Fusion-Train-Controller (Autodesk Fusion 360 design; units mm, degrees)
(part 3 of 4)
sketch "Close old plate mounting hole (1)" plane through (24, 0, 0) normal (1, 0, 0) x axis (0, 0, -1)
  circle C1 centre (-44, -51) radius 1.71
extrude "Extrude19" add sketch "Close old plate mounting hole (1)" along normal blind 12
work_plane "WorkPlane20" AlongDistance 23.9 ExtraOffset 0
sketch "Raised M3 block fastener (1)" plane through (23.9, 0, 0) normal (1, 0, 0) x axis (0, 0, -1)
  circle C1 centre (-52, -51) radius 1.7
extrude "Extrude20" cut sketch "Raised M3 block fastener (1)" along normal blind 12.2
work_plane "WorkPlane20" AlongDistance 51.9 ExtraOffset 0
sketch "Continue adjuster bore" plane through (0, 0, 51.9) normal (0, 0, 1) x axis (1, 0, 0)
  circle C1 centre (12, -55) radius 2.2
extrude "Extrude20" cut sketch "Continue adjuster bore" along normal blind 5.2
work_plane "WorkPlane21" AlongDistance 51.9 ExtraOffset 0
sketch "Continue guide bore" plane through (0, 0, 51.9) normal (0, 0, 1) x axis (1, 0, 0)
  circle C1 centre (5, -55) radius 1.7
extrude "Extrude21" cut sketch "Continue guide bore" along normal blind 5.2
work_plane "WorkPlane22" AlongDistance 51.9 ExtraOffset 0
sketch "Continue guide bore (1)" plane through (0, 0, 51.9) normal (0, 0, 1) x axis (1, 0, 0)
  circle C1 centre (19, -55) radius 1.7
extrude "Extrude22" cut sketch "Continue guide bore (1)" along normal blind 5.2
work_plane "WorkPlane23" AlongDistance -24.1 ExtraOffset 0
sketch "Preserve cam sweep clearance" plane through (-24.1, 0, 0) normal (1, 0, 0) x axis (0, 0, -1)
  circle C1 centre (-65, 0) radius 51
extrude "Extrude23" cut sketch "Preserve cam sweep clearance" along normal blind 48.2
work_plane "WorkPlane11" AlongDistance 9 ExtraOffset 0
sketch "Clamp washer clearance at flange" plane through (0, 9, 0) normal (0, 1, 0) x axis (1, 0, 0)
  circle C1 centre (45.5, -73) radius 3.6
extrude "Extrude11" cut sketch "Clamp washer clearance at flange" along normal blind 2
work_plane "WorkPlane8" AlongDistance 37.25 ExtraOffset 0
sketch "Flat shoulder aligns with shaft print bed" plane through (37.25, 0, 0) normal (1, 0, 0) x axis (0, 0, -1)
  line L1 (-54, 11) -> (-54, 6.5)
  line L2 (-76, 11) -> (-54, 11)
  line L3 (-76, 6.5) -> (-76, 11)
  line L4 (-54, 6.5) -> (-76, 6.5)
extrude "Extrude8" cut sketch "Flat shoulder aligns with shaft print bed" along normal blind 3.2
work_plane "WorkPlane1" AlongDistance -23.85 ExtraOffset 0
sketch "Controlled rotor axial clearance" plane through (-23.85, 0, 0) normal (1, 0, 0) x axis (0, 0, -1)
  circle C1 centre (-65, 0) radius 10
extrude "Extrude1" new body sketch "Controlled rotor axial clearance" along normal blind 16.85 bodies "P23 Left rotor thrust spacer"
work_plane "WorkPlane2" AlongDistance -23.95 ExtraOffset 0
sketch "Free spacer bore" plane through (-23.95, 0, 0) normal (1, 0, 0) x axis (0, 0, -1)
  circle C1 centre (-65, 0) radius 8.2
extrude "Extrude2" cut sketch "Free spacer bore" along normal blind 17.05
work_plane "WorkPlane1" AlongDistance 7 ExtraOffset 0
sketch "Controlled rotor axial clearance" plane through (7, 0, 0) normal (1, 0, 0) x axis (0, 0, -1)
  circle C1 centre (-65, 0) radius 10
extrude "Extrude1" new body sketch "Controlled rotor axial clearance" along normal blind 16.85 bodies "P24 Right rotor thrust spacer"
work_plane "WorkPlane2" AlongDistance 6.9 ExtraOffset 0
sketch "Free spacer bore" plane through (6.9, 0, 0) normal (1, 0, 0) x axis (0, 0, -1)
  circle C1 centre (-65, 0) radius 8.2
extrude "Extrude2" cut sketch "Free spacer bore" along normal blind 17.05
work_plane "WorkPlane22" AlongDistance -76 ExtraOffset 0
sketch "Restore rail bolt clearance after hole filling" plane through (0, -76, 0) normal (0, 1, 0) x axis (1, 0, 0)
  circle C1 centre (-30, -45) radius 2.7
extrude "Extrude22" cut sketch "Restore rail bolt clearance after hole filling" along normal blind 22
work_plane "WorkPlane23" AlongDistance 54 ExtraOffset 0
sketch "Restore rail bolt clearance after hole filling (1)" plane through (0, 54, 0) normal (0, 1, 0) x axis (1, 0, 0)
  circle C1 centre (-30, -45) radius 2.7
work_plane "WorkPlane24" AlongDistance -55 ExtraOffset 0
sketch "Restore rail head access after hole filling" plane through (0, -55, 0) normal (0, 1, 0) x axis (1, 0, 0)
  circle C1 centre (-30, -45) radius 5.3
extrude "Extrude24" cut sketch "Restore rail head access after hole filling" along normal blind 12
work_plane "WorkPlane25" AlongDistance 43 ExtraOffset 0
sketch "Restore rail head access after hole filling (1)" plane through (0, 43, 0) normal (0, 1, 0) x axis (1, 0, 0)
  circle C1 centre (-30, -45) radius 5.3
work_plane "WorkPlane21" AlongDistance -76 ExtraOffset 0
sketch "Restore rail bolt clearance after hole filling" plane through (0, -76, 0) normal (0, 1, 0) x axis (1, 0, 0)
  circle C1 centre (30, -45) radius 2.7
extrude "Extrude21" cut sketch "Restore rail bolt clearance after hole filling" along normal blind 22
work_plane "WorkPlane22" AlongDistance 54 ExtraOffset 0
sketch "Restore rail bolt clearance after hole filling (1)" plane through (0, 54, 0) normal (0, 1, 0) x axis (1, 0, 0)
  circle C1 centre (30, -45) radius 2.7
work_plane "WorkPlane23" AlongDistance -55 ExtraOffset 0
sketch "Restore rail head access after hole filling" plane through (0, -55, 0) normal (0, 1, 0) x axis (1, 0, 0)
  circle C1 centre (30, -45) radius 5.3
extrude "Extrude23" cut sketch "Restore rail head access after hole filling" along normal blind 12
work_plane "WorkPlane24" AlongDistance 43 ExtraOffset 0
sketch "Restore rail head access after hole filling (1)" plane through (0, 43, 0) normal (0, 1, 0) x axis (1, 0, 0)
  circle C1 centre (30, -45) radius 5.3
work_plane "WorkPlane14" AlongDistance -18.1 ExtraOffset 0
sketch "Stop lug clearance for concentric thrust spacer" plane through (-18.1, 0, 0) normal (1, 0, 0) x axis (0, 0, -1)
  circle C1 centre (-65, 0) radius 10.2
extrude "Extrude14" cut sketch "Stop lug clearance for concentric thrust spacer" along normal blind 11
work_plane "WorkPlane15" AlongDistance -18.1 ExtraOffset 0
sketch "Complete stop lug relief to rotor face" plane through (-18.1, 0, 0) normal (1, 0, 0) x axis (0, 0, -1)
  circle C1 centre (-65, 0) radius 10.2
extrude "Extrude15" cut sketch "Complete stop lug relief to rotor face" along normal blind 11.1
ground "Pin2"
ground "Pin3"
ground "Pin4"
ground "Pin5"
ground "Pin6"
ground "Pin7"
ground "Pin8"
ground "Pin9"
ground "Pin10"
ground "Pin11"
ground "Pin12"
ground "Pin13"
ground "Pin14"
ground "Pin26"
ground "Pin31"
ground "Pin32"
ground "Pin33"
ground "Pin34"
ground "Pin35"
ground "Pin36"
ground "Pin48"
ground "Pin49"
work_plane "WorkPlane24" AlongDistance -24 ExtraOffset 0
sketch "Extra roof over relocated heat-set inserts" plane through (-24, 0, 0) normal (1, 0, 0) x axis (0, 0, -1)
  line L1 (-57, -44) -> (-57, -66)
  line L2 (-59, -44) -> (-57, -44)
  line L3 (-59, -66) -> (-59, -44)
  line L4 (-57, -66) -> (-59, -66)
extrude "Extrude24" add sketch "Extra roof over relocated heat-set inserts" along normal blind 48
work_plane "WorkPlane25" AlongDistance -24 ExtraOffset 0
sketch "Fill former insert location" plane through (-24, 0, 0) normal (1, 0, 0) x axis (0, 0, -1)
  circle C1 centre (-52, -59) radius 2.01
extrude "Extrude25" add sketch "Fill former insert location" along normal blind 8.7
work_plane "WorkPlane26" AlongDistance 15.3 ExtraOffset 0
sketch "Fill former insert location (1)" plane through (15.3, 0, 0) normal (1, 0, 0) x axis (0, 0, -1)
  circle C1 centre (-52, -59) radius 2.01
extrude "Extrude26" add sketch "Fill former insert location (1)" along normal blind 8.7
work_plane "WorkPlane26" AlongDistance -36 ExtraOffset 0
sketch "Fill former plate mounting hole" plane through (-36, 0, 0) normal (1, 0, 0) x axis (0, 0, -1)
  circle C1 centre (-52, -59) radius 1.71
extrude "Extrude26" add sketch "Fill former plate mounting hole" along normal blind 12
work_plane "WorkPlane25" AlongDistance 24 ExtraOffset 0
sketch "Fill former plate mounting hole" plane through (24, 0, 0) normal (1, 0, 0) x axis (0, 0, -1)
  circle C1 centre (-52, -59) radius 1.71
extrude "Extrude25" add sketch "Fill former plate mounting hole" along normal blind 12
work_plane "WorkPlane27" AlongDistance -24 ExtraOffset 0
sketch "Fill former insert location (2)" plane through (-24, 0, 0) normal (1, 0, 0) x axis (0, 0, -1)
  circle C1 centre (-52, -51) radius 2.01
extrude "Extrude27" add sketch "Fill former insert location (2)" along normal blind 8.7
work_plane "WorkPlane28" AlongDistance 15.3 ExtraOffset 0
sketch "Fill former insert location (3)" plane through (15.3, 0, 0) normal (1, 0, 0) x axis (0, 0, -1)
  circle C1 centre (-52, -51) radius 2.01
extrude "Extrude28" add sketch "Fill former insert location (3)" along normal blind 8.7
work_plane "WorkPlane27" AlongDistance -36 ExtraOffset 0
sketch "Fill former plate mounting hole (1)" plane through (-36, 0, 0) normal (1, 0, 0) x axis (0, 0, -1)
  circle C1 centre (-52, -51) radius 1.71
extrude "Extrude27" add sketch "Fill former plate mounting hole (1)" along normal blind 12
work_plane "WorkPlane26" AlongDistance 24 ExtraOffset 0
sketch "Fill former plate mounting hole (1)" plane through (24, 0, 0) normal (1, 0, 0) x axis (0, 0, -1)
  circle C1 centre (-52, -51) radius 1.71
extrude "Extrude26" add sketch "Fill former plate mounting hole (1)" along normal blind 12
work_plane "WorkPlane29" AlongDistance -24.1 ExtraOffset 0
sketch "Relocated insert with cam-side retaining wall" plane through (-24.1, 0, 0) normal (1, 0, 0) x axis (0, 0, -1)
  circle C1 centre (-53.5, -62) radius 2
extrude "Extrude29" cut sketch "Relocated insert with cam-side retaining wall" along normal blind 8.9
work_plane "WorkPlane30" AlongDistance 15.3 ExtraOffset 0
sketch "Relocated insert with cam-side retaining wall (1)" plane through (15.3, 0, 0) normal (1, 0, 0) x axis (0, 0, -1)
  circle C1 centre (-53.5, -62) radius 2
extrude "Extrude30" cut sketch "Relocated insert with cam-side retaining wall (1)" along normal blind 8.9
work_plane "WorkPlane28" AlongDistance -36.1 ExtraOffset 0
sketch "Relocated mount above rail counterbore" plane through (-36.1, 0, 0) normal (1, 0, 0) x axis (0, 0, -1)
  circle C1 centre (-53.5, -62) radius 1.7
extrude "Extrude28" cut sketch "Relocated mount above rail counterbore" along normal blind 12.2
work_plane "WorkPlane27" AlongDistance 23.9 ExtraOffset 0
sketch "Relocated mount above rail counterbore" plane through (23.9, 0, 0) normal (1, 0, 0) x axis (0, 0, -1)
  circle C1 centre (-53.5, -62) radius 1.7
extrude "Extrude27" cut sketch "Relocated mount above rail counterbore" along normal blind 12.2
work_plane "WorkPlane31" AlongDistance -24.1 ExtraOffset 0
sketch "Relocated insert with cam-side retaining wall (2)" plane through (-24.1, 0, 0) normal (1, 0, 0) x axis (0, 0, -1)
  circle C1 centre (-53.5, -54) radius 2
extrude "Extrude31" cut sketch "Relocated insert with cam-side retaining wall (2)" along normal blind 8.9
work_plane "WorkPlane32" AlongDistance 15.3 ExtraOffset 0
sketch "Relocated insert with cam-side retaining wall (3)" plane through (15.3, 0, 0) normal (1, 0, 0) x axis (0, 0, -1)
  circle C1 centre (-53.5, -54) radius 2
extrude "Extrude32" cut sketch "Relocated insert with cam-side retaining wall (3)" along normal blind 8.9
work_plane "WorkPlane29" AlongDistance -36.1 ExtraOffset 0
sketch "Relocated mount above rail counterbore (1)" plane through (-36.1, 0, 0) normal (1, 0, 0) x axis (0, 0, -1)
  circle C1 centre (-53.5, -54) radius 1.7
extrude "Extrude29" cut sketch "Relocated mount above rail counterbore (1)" along normal blind 12.2
work_plane "WorkPlane28" AlongDistance 23.9 ExtraOffset 0
sketch "Relocated mount above rail counterbore (1)" plane through (23.9, 0, 0) normal (1, 0, 0) x axis (0, 0, -1)
  circle C1 centre (-53.5, -54) radius 1.7
extrude "Extrude28" cut sketch "Relocated mount above rail counterbore (1)" along normal blind 12.2
work_plane "WorkPlane33" AlongDistance 51.9 ExtraOffset 0
sketch "Continue adjuster bore through roof" plane through (0, 0, 51.9) normal (0, 0, 1) x axis (1, 0, 0)
  circle C1 centre (12, -55) radius 2.2
extrude "Extrude33" cut sketch "Continue adjuster bore through roof" along normal blind 7.2
work_plane "WorkPlane34" AlongDistance 51.9 ExtraOffset 0
sketch "Continue guide bore through roof" plane through (0, 0, 51.9) normal (0, 0, 1) x axis (1, 0, 0)
  circle C1 centre (5, -55) radius 1.7
extrude "Extrude34" cut sketch "Continue guide bore through roof" along normal blind 7.2
work_plane "WorkPlane35" AlongDistance 51.9 ExtraOffset 0
sketch "Continue guide bore through roof (1)" plane through (0, 0, 51.9) normal (0, 0, 1) x axis (1, 0, 0)
  circle C1 centre (19, -55) radius 1.7
extrude "Extrude35" cut sketch "Continue guide bore through roof (1)" along normal blind 7.2
work_plane "WorkPlane36" AlongDistance -24.1 ExtraOffset 0
sketch "Restore cam envelope after pocket repair" plane through (-24.1, 0, 0) normal (1, 0, 0) x axis (0, 0, -1)
  circle C1 centre (-65, 0) radius 51
extrude "Extrude36" cut sketch "Restore cam envelope after pocket repair" along normal blind 48.2
work_plane "WorkPlane30" AlongDistance -76 ExtraOffset 0
sketch "Preserve rail shank passage" plane through (0, -76, 0) normal (0, 1, 0) x axis (1, 0, 0)
  circle C1 centre (-30, -45) radius 2.7
work_plane "WorkPlane31" AlongDistance 54 ExtraOffset 0
sketch "Preserve rail shank passage (1)" plane through (0, 54, 0) normal (0, 1, 0) x axis (1, 0, 0)
  circle C1 centre (-30, -45) radius 2.7
work_plane "WorkPlane32" AlongDistance -55 ExtraOffset 0
sketch "Preserve rail head passage" plane through (0, -55, 0) normal (0, 1, 0) x axis (1, 0, 0)
  circle C1 centre (-30, -45) radius 5.3
extrude "Extrude32" cut sketch "Preserve rail head passage" along normal blind 12
work_plane "WorkPlane33" AlongDistance 43 ExtraOffset 0
sketch "Preserve rail head passage (1)" plane through (0, 43, 0) normal (0, 1, 0) x axis (1, 0, 0)
  circle C1 centre (-30, -45) radius 5.3
work_plane "WorkPlane29" AlongDistance -76 ExtraOffset 0
sketch "Preserve rail shank passage" plane through (0, -76, 0) normal (0, 1, 0) x axis (1, 0, 0)
  circle C1 centre (30, -45) radius 2.7
work_plane "WorkPlane30" AlongDistance 54 ExtraOffset 0
sketch "Preserve rail shank passage (1)" plane through (0, 54, 0) normal (0, 1, 0) x axis (1, 0, 0)
  circle C1 centre (30, -45) radius 2.7
work_plane "WorkPlane31" AlongDistance -55 ExtraOffset 0
sketch "Preserve rail head passage" plane through (0, -55, 0) normal (0, 1, 0) x axis (1, 0, 0)
  circle C1 centre (30, -45) radius 5.3
extrude "Extrude31" cut sketch "Preserve rail head passage" along normal blind 12
work_plane "WorkPlane32" AlongDistance 43 ExtraOffset 0
sketch "Preserve rail head passage (1)" plane through (0, 43, 0) normal (0, 1, 0) x axis (1, 0, 0)
  circle C1 centre (30, -45) radius 5.3
work_plane "WorkPlane1" AlongDistance 59 ExtraOffset 0
sketch "One mm extra preload limit" plane through (0, 0, 59) normal (0, 0, 1) x axis (1, 0, 0)
  circle C1 centre (12, -55) radius 3.3
extrude "Extrude1" new body sketch "One mm extra preload limit" along normal blind 2 bodies "P15 Preload limit collar 2 mm"
work_plane "WorkPlane2" AlongDistance 58.9 ExtraOffset 0
sketch "M4 clearance" plane through (0, 0, 58.9) normal (0, 0, 1) x axis (1, 0, 0)
  circle C1 centre (12, -55) radius 2.25
extrude "Extrude2" cut sketch "M4 clearance" along normal blind 2.2
work_plane "WorkPlane1" AlongDistance 32 ExtraOffset 0
sketch "Cup guide M3x35 5" plane through (0, 0, 32) normal (0, 0, 1) x axis (1, 0, 0)
  circle C1 centre (5, -55) radius 1.5
extrude "Extrude1" new body sketch "Cup guide M3x35 5" along normal blind 35 bodies "HARDWARE Cup guide M3x35 5"
work_plane "WorkPlane2" AlongDistance 30.35 ExtraOffset 0
sketch "Button head" plane through (0, 0, 30.35) normal (0, 0, 1) x axis (1, 0, 0)
  circle C1 centre (5, -55) radius 2.85
extrude "Extrude2" add sketch "Button head" along normal blind 1.65
work_plane "WorkPlane1" AlongDistance 59 ExtraOffset 0
sketch "Cup guide washer 5" plane through (0, 0, 59) normal (0, 0, 1) x axis (1, 0, 0)
  circle C1 centre (5, -55) radius 3.5
extrude "Extrude1" new body sketch "Cup guide washer 5" along normal blind 0.5 bodies "HARDWARE Cup guide washer 5"
work_plane "WorkPlane2" AlongDistance 58.9 ExtraOffset 0
sketch "Washer clearance" plane through (0, 0, 58.9) normal (0, 0, 1) x axis (1, 0, 0)
  circle C1 centre (5, -55) radius 1.7
extrude "Extrude2" cut sketch "Washer clearance" along normal blind 0.7
work_plane "WorkPlane1" AlongDistance 59.5 ExtraOffset 0
sketch "Cup guide M3 nut 5" plane through (0, 0, 59.5) normal (0, 0, 1) x axis (1, 0, 0)
  line L1 (6.5877, -52.25) -> (8.1754, -55)
  line L2 (3.4123, -52.25) -> (6.5877, -52.25)
  line L3 (1.8246, -55) -> (3.4123, -52.25)
  line L4 (3.4123, -57.75) -> (1.8246, -55)
  line L5 (6.5877, -57.75) -> (3.4123, -57.75)
  line L6 (8.1754, -55) -> (6.5877, -57.75)
extrude "Extrude1" new body sketch "Cup guide M3 nut 5" along normal blind 2.4 bodies "HARDWARE Cup guide M3 nut 5"
work_plane "WorkPlane2" AlongDistance 59.4 ExtraOffset 0
sketch "Thread envelope" plane through (0, 0, 59.4) normal (0, 0, 1) x axis (1, 0, 0)
  circle C1 centre (5, -55) radius 1.5
extrude "Extrude2" cut sketch "Thread envelope" along normal blind 2.6
work_plane "WorkPlane1" AlongDistance 32 ExtraOffset 0
sketch "Cup guide M3x35 19" plane through (0, 0, 32) normal (0, 0, 1) x axis (1, 0, 0)
  circle C1 centre (19, -55) radius 1.5
extrude "Extrude1" new body sketch "Cup guide M3x35 19" along normal blind 35 bodies "HARDWARE Cup guide M3x35 19"
work_plane "WorkPlane2" AlongDistance 30.35 ExtraOffset 0
sketch "Button head" plane through (0, 0, 30.35) normal (0, 0, 1) x axis (1, 0, 0)
  circle C1 centre (19, -55) radius 2.85
extrude "Extrude2" add sketch "Button head" along normal blind 1.65
work_plane "WorkPlane1" AlongDistance 59 ExtraOffset 0
sketch "Cup guide washer 19" plane through (0, 0, 59) normal (0, 0, 1) x axis (1, 0, 0)
  circle C1 centre (19, -55) radius 3.5
extrude "Extrude1" new body sketch "Cup guide washer 19" along normal blind 0.5 bodies "HARDWARE Cup guide washer 19"
work_plane "WorkPlane2" AlongDistance 58.9 ExtraOffset 0
sketch "Washer clearance" plane through (0, 0, 58.9) normal (0, 0, 1) x axis (1, 0, 0)
  circle C1 centre (19, -55) radius 1.7
extrude "Extrude2" cut sketch "Washer clearance" along normal blind 0.7
work_plane "WorkPlane1" AlongDistance 59.5 ExtraOffset 0
sketch "Cup guide M3 nut 19" plane through (0, 0, 59.5) normal (0, 0, 1) x axis (1, 0, 0)
  line L1 (20.5877, -52.25) -> (22.1754, -55)
  line L2 (17.4123, -52.25) -> (20.5877, -52.25)
  line L3 (15.8246, -55) -> (17.4123, -52.25)
  line L4 (17.4123, -57.75) -> (15.8246, -55)
  line L5 (20.5877, -57.75) -> (17.4123, -57.75)
  line L6 (22.1754, -55) -> (20.5877, -57.75)
extrude "Extrude1" new body sketch "Cup guide M3 nut 19" along normal blind 2.4 bodies "HARDWARE Cup guide M3 nut 19"
work_plane "WorkPlane2" AlongDistance 59.4 ExtraOffset 0
sketch "Thread envelope" plane through (0, 0, 59.4) normal (0, 0, 1) x axis (1, 0, 0)
  circle C1 centre (19, -55) radius 1.5
extrude "Extrude2" cut sketch "Thread envelope" along normal blind 2.6
work_plane "WorkPlane1" AlongDistance -36 ExtraOffset 0
sketch "Spring block M3x20 (-62, -1)" plane through (-36, 0, 0) normal (1, 0, 0) x axis (0, 0, -1)
  circle C1 centre (-53.5, -62) radius 1.5
extrude "Extrude1" new body sketch "Spring block M3x20 (-62, -1)" along normal blind 20 bodies "HARDWARE Spring block M3x20 (-62, -1)"
work_plane "WorkPlane2" AlongDistance -37.65 ExtraOffset 0
sketch "Button head" plane through (-37.65, 0, 0) normal (1, 0, 0) x axis (0, 0, -1)
  circle C1 centre (-53.5, -62) radius 2.85
extrude "Extrude2" add sketch "Button head" along normal blind 1.65
work_plane "WorkPlane1" AlongDistance 16 ExtraOffset 0
sketch "Spring block M3x20 (-62, 1)" plane through (16, 0, 0) normal (1, 0, 0) x axis (0, 0, -1)
  circle C1 centre (-53.5, -62) radius 1.5
extrude "Extrude1" new body sketch "Spring block M3x20 (-62, 1)" along normal blind 20 bodies "HARDWARE Spring block M3x20 (-62, 1)"
work_plane "WorkPlane2" AlongDistance 36 ExtraOffset 0
sketch "Button head" plane through (36, 0, 0) normal (1, 0, 0) x axis (0, 0, -1)
  circle C1 centre (-53.5, -62) radius 2.85
extrude "Extrude2" add sketch "Button head" along normal blind 1.65
work_plane "WorkPlane1" AlongDistance 37 ExtraOffset 0
sketch "Preload adjuster M4x25 SOCKET HEAD" plane through (0, 0, 37) normal (0, 0, 1) x axis (1, 0, 0)
  circle C1 centre (12, -55) radius 2
extrude "Extrude1" new body sketch "Preload adjuster M4x25 SOCKET HEAD" along normal blind 25 bodies "HARDWARE Preload adjuster M4x25 SOCKET HEAD"
work_plane "WorkPlane2" AlongDistance 62 ExtraOffset 0
sketch "Button head" plane through (0, 0, 62) normal (0, 0, 1) x axis (1, 0, 0)
  circle C1 centre (12, -55) radius 3.5
extrude "Extrude2" add sketch "Button head" along normal blind 4
work_plane "WorkPlane16" AlongDistance -5 ExtraOffset 0
sketch "Flat washer seat for sensor-drive shaft clamp" plane through (-5, 0, 0) normal (1, 0, 0) x axis (0, 0, -1)
  line L1 (-60, 22) -> (-60, 20)
  line L2 (-70, 22) -> (-60, 22)
  line L3 (-70, 20) -> (-70, 22)
  line L4 (-60, 20) -> (-70, 20)
extrude "Extrude16" add sketch "Flat washer seat for sensor-drive shaft clamp" along normal blind 10
work_plane "WorkPlane17" AlongDistance 6.4 ExtraOffset 0
sketch "Radial screw onto printed shaft D flat" plane through (0, 6.4, 0) normal (0, 1, 0) x axis (1, 0, 0)
  circle C1 centre (0, -65) radius 1.7
extrude "Extrude17" cut sketch "Radial screw onto printed shaft D flat" along normal blind 15.7
work_plane "WorkPlane18" AlongDistance 15.2 ExtraOffset 0
sketch "M3 heatset pocket for rotor clamp" plane through (0, 15.2, 0) normal (0, 1, 0) x axis (1, 0, 0)
  circle C1 centre (0, -65) radius 2
extrude "Extrude18" cut sketch "M3 heatset pocket for rotor clamp" along normal blind 6.9
work_plane "WorkPlane1" AlongDistance 6.5 ExtraOffset 0
sketch "Rotor clamp M3x16" plane through (0, 6.5, 0) normal (0, 1, 0) x axis (1, 0, 0)
  circle C1 centre (0, -65) radius 1.5
extrude "Extrude1" new body sketch "Rotor clamp M3x16" along normal blind 16 bodies "HARDWARE Rotor clamp M3x16"
work_plane "WorkPlane2" AlongDistance 22.5 ExtraOffset 0
sketch "Button head" plane through (0, 22.5, 0) normal (0, 1, 0) x axis (1, 0, 0)
  circle C1 centre (0, -65) radius 2.85
extrude "Extrude2" add sketch "Button head" along normal blind 1.65
work_plane "WorkPlane1" AlongDistance 22 ExtraOffset 0
sketch "Rotor clamp M3 washer" plane through (0, 22, 0) normal (0, 1, 0) x axis (1, 0, 0)
  circle C1 centre (0, -65) radius 3.5
extrude "Extrude1" new body sketch "Rotor clamp M3 washer" along normal blind 0.5 bodies "HARDWARE Rotor clamp M3 washer"
work_plane "WorkPlane2" AlongDistance 21.9 ExtraOffset 0
sketch "Washer clearance" plane through (0, 21.9, 0) normal (0, 1, 0) x axis (1, 0, 0)
  circle C1 centre (0, -65) radius 1.7
extrude "Extrude2" cut sketch "Washer clearance" along normal blind 0.7
work_plane "WorkPlane4" AlongDistance 51.9 ExtraOffset 0
sketch "Input slot 4.2 mm - tune running fit" plane through (51.9, 0, 0) normal (1, 0, 0) x axis (0, 0, -1)
  line L1 (-62.9, 13) -> (-62.9, -13)
  line L2 (-67.1, 13) -> (-62.9, 13)
  line L3 (-67.1, -13) -> (-67.1, 13)
  line L4 (-62.9, -13) -> (-67.1, -13)
extrude "Extrude4" cut sketch "Input slot 4.2 mm - tune running fit" along normal blind 2.6
work_plane "WorkPlane5" AlongDistance 57.5 ExtraOffset 0
sketch "Output slot 4.2 mm - tune running fit" plane through (57.5, 0, 0) normal (1, 0, 0) x axis (0, 0, -1)
  line L1 (-52, 2.1) -> (-52, -2.1)
  line L2 (-78, 2.1) -> (-52, 2.1)
  line L3 (-78, -2.1) -> (-78, 2.1)
  line L4 (-52, -2.1) -> (-78, -2.1)
extrude "Extrude5" cut sketch "Output slot 4.2 mm - tune running fit" along normal blind 2.6
work_plane "WorkPlane1" AlongDistance 52 ExtraOffset 0
sketch "Optional closer running fit" plane through (52, 0, 0) normal (1, 0, 0) x axis (0, 0, -1)
  circle C1 centre (-65, 0) radius 12
extrude "Extrude1" new body sketch "Optional closer running fit" along normal blind 8 bodies "P18 Tight fit alternate disc - 4.1 mm slots"
work_plane "WorkPlane2" AlongDistance 51.9 ExtraOffset 0
sketch "Input 4.1 slot" plane through (51.9, 0, 0) normal (1, 0, 0) x axis (0, 0, -1)
  line L1 (-62.95, 13) -> (-62.95, -13)
  line L2 (-67.05, 13) -> (-62.95, 13)
  line L3 (-67.05, -13) -> (-67.05, 13)
  line L4 (-62.95, -13) -> (-67.05, -13)
extrude "Extrude2" cut sketch "Input 4.1 slot" along normal blind 2.6
work_plane "WorkPlane3" AlongDistance 57.5 ExtraOffset 0
sketch "Output 4.1 slot" plane through (57.5, 0, 0) normal (1, 0, 0) x axis (0, 0, -1)
  line L1 (-52, 2.05) -> (-52, -2.05)
  line L2 (-78, 2.05) -> (-52, 2.05)
  line L3 (-78, -2.05) -> (-78, 2.05)
  line L4 (-52, -2.05) -> (-78, -2.05)
extrude "Extrude3" cut sketch "Output 4.1 slot" along normal blind 2.6
work_plane "WorkPlane37" AlongDistance -24 ExtraOffset 0
sketch "Extend reaction block into free rail bay" plane through (-24, 0, 0) normal (1, 0, 0) x axis (0, 0, -1)
  line L1 (-38, -66) -> (-38, -74)
  line L2 (-59, -66) -> (-38, -66)
  line L3 (-59, -74) -> (-59, -66)
  line L4 (-38, -74) -> (-59, -74)
extrude "Extrude37" add sketch "Extend reaction block into free rail bay" along normal blind 48
work_plane "WorkPlane38" AlongDistance -24 ExtraOffset 0
sketch "Close mounting bore that crossed cup guide" plane through (-24, 0, 0) normal (1, 0, 0) x axis (0, 0, -1)
  circle C1 centre (-53.5, -54) radius 2.01
extrude "Extrude38" add sketch "Close mounting bore that crossed cup guide" along normal blind 8.7
work_plane "WorkPlane39" AlongDistance -24.1 ExtraOffset 0
sketch "Outer mounting row clear of guide" plane through (-24.1, 0, 0) normal (1, 0, 0) x axis (0, 0, -1)
  circle C1 centre (-53.5, -70) radius 2
extrude "Extrude39" cut sketch "Outer mounting row clear of guide" along normal blind 8.9
work_plane "WorkPlane40" AlongDistance 15.3 ExtraOffset 0
sketch "Close mounting bore that crossed cup guide (1)" plane through (15.3, 0, 0) normal (1, 0, 0) x axis (0, 0, -1)
  circle C1 centre (-53.5, -54) radius 2.01
extrude "Extrude40" add sketch "Close mounting bore that crossed cup guide (1)" along normal blind 8.7
work_plane "WorkPlane41" AlongDistance 15.2 ExtraOffset 0
sketch "Outer mounting row clear of guide (1)" plane through (15.2, 0, 0) normal (1, 0, 0) x axis (0, 0, -1)
  circle C1 centre (-53.5, -70) radius 2
extrude "Extrude41" cut sketch "Outer mounting row clear of guide (1)" along normal blind 8.9
work_plane "WorkPlane34" AlongDistance -36 ExtraOffset 0
sketch "Close former inner mounting hole" plane through (-36, 0, 0) normal (1, 0, 0) x axis (0, 0, -1)
  circle C1 centre (-53.5, -54) radius 1.71
extrude "Extrude34" add sketch "Close former inner mounting hole" along normal blind 12
work_plane "WorkPlane35" AlongDistance -36.1 ExtraOffset 0
sketch "Matched outer mounting row" plane through (-36.1, 0, 0) normal (1, 0, 0) x axis (0, 0, -1)
  circle C1 centre (-53.5, -70) radius 1.7
extrude "Extrude35" cut sketch "Matched outer mounting row" along normal blind 12.2
work_plane "WorkPlane33" AlongDistance 24 ExtraOffset 0
sketch "Close former inner mounting hole" plane through (24, 0, 0) normal (1, 0, 0) x axis (0, 0, -1)
  circle C1 centre (-53.5, -54) radius 1.71
extrude "Extrude33" add sketch "Close former inner mounting hole" along normal blind 12
work_plane "WorkPlane34" AlongDistance 23.9 ExtraOffset 0
sketch "Matched outer mounting row" plane through (23.9, 0, 0) normal (1, 0, 0) x axis (0, 0, -1)
  circle C1 centre (-53.5, -70) radius 1.7
extrude "Extrude34" cut sketch "Matched outer mounting row" along normal blind 12.2
work_plane "WorkPlane42" AlongDistance 37.9 ExtraOffset 0
sketch "Restore separate cup guide bore" plane through (0, 0, 37.9) normal (0, 0, 1) x axis (1, 0, 0)
  circle C1 centre (5, -55) radius 1.7
work_plane "WorkPlane43" AlongDistance 37.9 ExtraOffset 0
sketch "Restore separate cup guide bore (1)" plane through (0, 0, 37.9) normal (0, 0, 1) x axis (1, 0, 0)
  circle C1 centre (19, -55) radius 1.7
extrude "Extrude43" cut sketch "Restore separate cup guide bore (1)" along normal blind 21.2
work_plane "WorkPlane44" AlongDistance -24.1 ExtraOffset 0
sketch "Preserve cam envelope" plane through (-24.1, 0, 0) normal (1, 0, 0) x axis (0, 0, -1)
  circle C1 centre (-65, 0) radius 51
work_plane "WorkPlane1" AlongDistance -36 ExtraOffset 0
sketch "Spring block M3x20 (-70, -1)" plane through (-36, 0, 0) normal (1, 0, 0) x axis (0, 0, -1)
  circle C1 centre (-53.5, -70) radius 1.5
extrude "Extrude1" new body sketch "Spring block M3x20 (-70, -1)" along normal blind 20 bodies "HARDWARE Spring block M3x20 (-70, -1)"
work_plane "WorkPlane2" AlongDistance -37.65 ExtraOffset 0
sketch "Button head" plane through (-37.65, 0, 0) normal (1, 0, 0) x axis (0, 0, -1)
  circle C1 centre (-53.5, -70) radius 2.85
extrude "Extrude2" add sketch "Button head" along normal blind 1.65
work_plane "WorkPlane1" AlongDistance 16 ExtraOffset 0
sketch "Spring block M3x20 (-70, 1)" plane through (16, 0, 0) normal (1, 0, 0) x axis (0, 0, -1)
  circle C1 centre (-53.5, -70) radius 1.5
extrude "Extrude1" new body sketch "Spring block M3x20 (-70, 1)" along normal blind 20 bodies "HARDWARE Spring block M3x20 (-70, 1)"
work_plane "WorkPlane2" AlongDistance 36 ExtraOffset 0
sketch "Button head" plane through (36, 0, 0) normal (1, 0, 0) x axis (0, 0, -1)
  circle C1 centre (-53.5, -70) radius 2.85
extrude "Extrude2" add sketch "Button head" along normal blind 1.65
ground "Pin50"
ground "Pin51"
ground "Pin52"
ground "Pin53"
ground "Pin54"
ground "Pin55"
ground "Pin56"
ground "Pin57"
ground "Pin58"
ground "Pin59"
ground "Pin68"
ground "Pin69"
as_built_joint "As-built6"
as_built_joint "As-built7"
as_built_joint "As-built8" RotateMinimum -52 RotateMaximum 52
as_built_joint "As-built9" RotateMinimum -6 RotateMaximum 1
as_built_joint "As-built10"
work_plane "WorkPlane36" AlongDistance -55 ExtraOffset 0
sketch "Close inaccessible rail head pocket" plane through (0, -55, 0) normal (0, 1, 0) x axis (1, 0, 0)
  circle C1 centre (-30, -45) radius 5.31
extrude "Extrude36" add sketch "Close inaccessible rail head pocket" along normal blind 12
work_plane "WorkPlane37" AlongDistance 43 ExtraOffset 0
sketch "Close inaccessible rail head pocket (1)" plane through (0, 43, 0) normal (0, 1, 0) x axis (1, 0, 0)
  circle C1 centre (-30, -45) radius 5.31
extrude "Extrude37" add sketch "Close inaccessible rail head pocket (1)" along normal blind 12
work_plane "WorkPlane38" AlongDistance -75 ExtraOffset 0
sketch "Close obsolete side rail bore" plane through (0, -75, 0) normal (0, 1, 0) x axis (1, 0, 0)
  circle C1 centre (-30, -45) radius 2.71
extrude "Extrude38" add sketch "Close obsolete side rail bore" along normal blind 20
work_plane "WorkPlane39" AlongDistance 55 ExtraOffset 0
sketch "Close obsolete side rail bore (1)" plane through (0, 55, 0) normal (0, 1, 0) x axis (1, 0, 0)
  circle C1 centre (-30, -45) radius 2.71
extrude "Extrude39" add sketch "Close obsolete side rail bore (1)" along normal blind 20
work_plane "WorkPlane40" AlongDistance -36 ExtraOffset 0
sketch "Top-access 2020 mounting flange" plane through (-36, 0, 0) normal (1, 0, 0) x axis (0, 0, -1)
  line L1 (-55, -70) -> (-55, -95)
  line L2 (-63, -70) -> (-55, -70)
  line L3 (-63, -95) -> (-63, -70)
  line L4 (-55, -95) -> (-63, -95)
extrude "Extrude40" add sketch "Top-access 2020 mounting flange" along normal blind 12
work_plane "WorkPlane41" AlongDistance -36 ExtraOffset 0
sketch "Mount root triangular reinforcement" plane through (-36, 0, 0) normal (1, 0, 0) x axis (0, 0, -1)
  line L1 (-56, -63) -> (-56, -70)
  line L2 (-63, -70) -> (-56, -63)
  line L3 (-56, -70) -> (-63, -70)
extrude "Extrude41" add sketch "Mount root triangular reinforcement" along normal blind 12
work_plane "WorkPlane42" AlongDistance 54.9 ExtraOffset 0
sketch "Vertical M5 rail mounting bore" plane through (0, 0, 54.9) normal (0, 0, 1) x axis (1, 0, 0)
  circle C1 centre (-30, -85) radius 2.7
extrude "Extrude42" cut sketch "Vertical M5 rail mounting bore" along normal blind 8.2
work_plane "WorkPlane43" AlongDistance -36 ExtraOffset 0
sketch "Top-access 2020 mounting flange (1)" plane through (-36, 0, 0) normal (1, 0, 0) x axis (0, 0, -1)
  line L1 (-55, 95) -> (-55, 70)
  line L2 (-63, 95) -> (-55, 95)
  line L3 (-63, 70) -> (-63, 95)
  line L4 (-55, 70) -> (-63, 70)
extrude "Extrude43" add sketch "Top-access 2020 mounting flange (1)" along normal blind 12
work_plane "WorkPlane44" AlongDistance -36 ExtraOffset 0
sketch "Mount root triangular reinforcement (1)" plane through (-36, 0, 0) normal (1, 0, 0) x axis (0, 0, -1)
  line L1 (-56, 70) -> (-56, 63)
  line L2 (-63, 70) -> (-56, 70)
  line L3 (-56, 63) -> (-63, 70)
extrude "Extrude44" add sketch "Mount root triangular reinforcement (1)" along normal blind 12
work_plane "WorkPlane45" AlongDistance 54.9 ExtraOffset 0
sketch "Vertical M5 rail mounting bore (1)" plane through (0, 0, 54.9) normal (0, 0, 1) x axis (1, 0, 0)
  circle C1 centre (-30, 85) radius 2.7
extrude "Extrude45" cut sketch "Vertical M5 rail mounting bore (1)" along normal blind 8.2
work_plane "WorkPlane46" AlongDistance -36 ExtraOffset 0
sketch "Close old M5 pivot clearance" plane through (-36, 0, 0) normal (1, 0, 0) x axis (0, 0, -1)
  circle C1 centre (-12, -35) radius 2.71
extrude "Extrude46" add sketch "Close old M5 pivot clearance" along normal blind 12
work_plane "WorkPlane47" AlongDistance -36.1 ExtraOffset 0
sketch "M3 follower pivot clearance" plane through (-36.1, 0, 0) normal (1, 0, 0) x axis (0, 0, -1)
  circle C1 centre (-12, -35) radius 1.7
extrude "Extrude47" cut sketch "M3 follower pivot clearance" along normal blind 12.2
work_plane "WorkPlane35" AlongDistance -55 ExtraOffset 0
sketch "Close inaccessible rail head pocket" plane through (0, -55, 0) normal (0, 1, 0) x axis (1, 0, 0)
  circle C1 centre (30, -45) radius 5.31
extrude "Extrude35" add sketch "Close inaccessible rail head pocket" along normal blind 12
work_plane "WorkPlane36" AlongDistance 43 ExtraOffset 0
sketch "Close inaccessible rail head pocket (1)" plane through (0, 43, 0) normal (0, 1, 0) x axis (1, 0, 0)
  circle C1 centre (30, -45) radius 5.31
extrude "Extrude36" add sketch "Close inaccessible rail head pocket (1)" along normal blind 12
work_plane "WorkPlane37" AlongDistance -75 ExtraOffset 0
sketch "Close obsolete side rail bore" plane through (0, -75, 0) normal (0, 1, 0) x axis (1, 0, 0)
  circle C1 centre (30, -45) radius 2.71
extrude "Extrude37" add sketch "Close obsolete side rail bore" along normal blind 20
work_plane "WorkPlane38" AlongDistance 55 ExtraOffset 0
sketch "Close obsolete side rail bore (1)" plane through (0, 55, 0) normal (0, 1, 0) x axis (1, 0, 0)
  circle C1 centre (30, -45) radius 2.71
extrude "Extrude38" add sketch "Close obsolete side rail bore (1)" along normal blind 20
work_plane "WorkPlane39" AlongDistance 24 ExtraOffset 0
sketch "Top-access 2020 mounting flange" plane through (24, 0, 0) normal (1, 0, 0) x axis (0, 0, -1)
  line L1 (-55, -70) -> (-55, -95)
  line L2 (-63, -70) -> (-55, -70)
  line L3 (-63, -95) -> (-63, -70)
  line L4 (-55, -95) -> (-63, -95)
extrude "Extrude39" add sketch "Top-access 2020 mounting flange" along normal blind 12
work_plane "WorkPlane40" AlongDistance 24 ExtraOffset 0
sketch "Mount root triangular reinforcement" plane through (24, 0, 0) normal (1, 0, 0) x axis (0, 0, -1)
  line L1 (-56, -63) -> (-56, -70)
  line L2 (-63, -70) -> (-56, -63)
  line L3 (-56, -70) -> (-63, -70)
extrude "Extrude40" add sketch "Mount root triangular reinforcement" along normal blind 12
work_plane "WorkPlane41" AlongDistance 54.9 ExtraOffset 0
sketch "Vertical M5 rail mounting bore" plane through (0, 0, 54.9) normal (0, 0, 1) x axis (1, 0, 0)
  circle C1 centre (30, -85) radius 2.7
extrude "Extrude41" cut sketch "Vertical M5 rail mounting bore" along normal blind 8.2
work_plane "WorkPlane42" AlongDistance 24 ExtraOffset 0
sketch "Top-access 2020 mounting flange (1)" plane through (24, 0, 0) normal (1, 0, 0) x axis (0, 0, -1)
  line L1 (-55, 95) -> (-55, 70)
  line L2 (-63, 95) -> (-55, 95)
  line L3 (-63, 70) -> (-63, 95)
  line L4 (-55, 70) -> (-63, 70)
extrude "Extrude42" add sketch "Top-access 2020 mounting flange (1)" along normal blind 12
work_plane "WorkPlane43" AlongDistance 24 ExtraOffset 0
sketch "Mount root triangular reinforcement (1)" plane through (24, 0, 0) normal (1, 0, 0) x axis (0, 0, -1)
  line L1 (-56, 70) -> (-56, 63)
  line L2 (-63, 70) -> (-56, 70)
  line L3 (-56, 63) -> (-63, 70)
extrude "Extrude43" add sketch "Mount root triangular reinforcement (1)" along normal blind 12
work_plane "WorkPlane44" AlongDistance 54.9 ExtraOffset 0
sketch "Vertical M5 rail mounting bore (1)" plane through (0, 0, 54.9) normal (0, 0, 1) x axis (1, 0, 0)
  circle C1 centre (30, 85) radius 2.7
extrude "Extrude44" cut sketch "Vertical M5 rail mounting bore (1)" along normal blind 8.2
work_plane "WorkPlane45" AlongDistance 24 ExtraOffset 0
sketch "Close old M5 pivot clearance" plane through (24, 0, 0) normal (1, 0, 0) x axis (0, 0, -1)
  circle C1 centre (-12, -35) radius 2.71
extrude "Extrude45" add sketch "Close old M5 pivot clearance" along normal blind 12
work_plane "WorkPlane46" AlongDistance 23.9 ExtraOffset 0
sketch "M3 follower pivot clearance" plane through (23.9, 0, 0) normal (1, 0, 0) x axis (0, 0, -1)
  circle C1 centre (-12, -35) radius 1.7
extrude "Extrude46" cut sketch "M3 follower pivot clearance" along normal blind 12.2
work_plane "WorkPlane47" AlongDistance 23.9 ExtraOffset 0
sketch "Restore cam service opening after obsolete bore closure" plane through (23.9, 0, 0) normal (1, 0, 0) x axis (0, 0, -1)
  line L1 (-42.2047, 46.7373) -> (-43.8497, 47.5044)
  line L2 (-40.5875, 45.9133) -> (-42.2047, 46.7373)
  line L3 (-39, 45.0333) -> (-40.5875, 45.9133)
  line L4 (-37.4442, 44.0985) -> (-39, 45.0333)
  line L5 (-35.922, 43.11) -> (-37.4442, 44.0985)
  line L6 (-34.4352, 42.0689) -> (-35.922, 43.11)
  line L7 (-32.9856, 40.9766) -> (-34.4352, 42.0689)
  line L8 (-31.575, 39.8343) -> (-32.9856, 40.9766)
  line L9 (-30.2052, 38.6435) -> (-31.575, 39.8343)
  line L10 (-28.8778, 37.4057) -> (-30.2052, 38.6435)
  line L11 (-27.5943, 36.1222) -> (-28.8778, 37.4057)
  line L12 (-26.3565, 34.7948) -> (-27.5943, 36.1222)
  line L13 (-25.1657, 33.425) -> (-26.3565, 34.7948)
  line L14 (-24.0234, 32.0144) -> (-25.1657, 33.425)
  line L15 (-22.9311, 30.5648) -> (-24.0234, 32.0144)
  line L16 (-21.89, 29.078) -> (-22.9311, 30.5648)
  line L17 (-20.9015, 27.5558) -> (-21.89, 29.078)
  line L18 (-19.9667, 26) -> (-20.9015, 27.5558)
  line L19 (-19.0867, 24.4125) -> (-19.9667, 26)
  line L20 (-18.2627, 22.7953) -> (-19.0867, 24.4125)
  line L21 (-17.4956, 21.1503) -> (-18.2627, 22.7953)
  line L22 (-16.7864, 19.4795) -> (-17.4956, 21.1503)
  line L23 (-16.136, 17.785) -> (-16.7864, 19.4795)
  line L24 (-15.5451, 16.0689) -> (-16.136, 17.785)
  line L25 (-15.0144, 14.3331) -> (-15.5451, 16.0689)
  line L26 (-14.5446, 12.5799) -> (-15.0144, 14.3331)
  line L27 (-14.1363, 10.8114) -> (-14.5446, 12.5799)
  line L28 (-13.79, 9.0297) -> (-14.1363, 10.8114)
  line L29 (-13.5061, 7.237) -> (-13.79, 9.0297)
  line L30 (-13.2849, 5.4355) -> (-13.5061, 7.237)
  line L31 (-13.1267, 3.6273) -> (-13.2849, 5.4355)
  line L32 (-13.0317, 1.8148) -> (-13.1267, 3.6273)
  line L33 (-13, 0) -> (-13.0317, 1.8148)
  line L34 (-13.0317, -1.8148) -> (-13, 0)
  line L35 (-13.1267, -3.6273) -> (-13.0317, -1.8148)
  line L36 (-13.2849, -5.4355) -> (-13.1267, -3.6273)
  line L37 (-13.5061, -7.237) -> (-13.2849, -5.4355)
  line L38 (-13.79, -9.0297) -> (-13.5061, -7.237)
  line L39 (-14.1363, -10.8114) -> (-13.79, -9.0297)
  line L40 (-14.5446, -12.5799) -> (-14.1363, -10.8114)
  line L41 (-15.0144, -14.3331) -> (-14.5446, -12.5799)
  line L42 (-15.5451, -16.0689) -> (-15.0144, -14.3331)
  line L43 (-16.136, -17.785) -> (-15.5451, -16.0689)
  line L44 (-16.7864, -19.4795) -> (-16.136, -17.785)
  line L45 (-17.4956, -21.1503) -> (-16.7864, -19.4795)
  line L46 (-18.2627, -22.7953) -> (-17.4956, -21.1503)
  line L47 (-19.0867, -24.4125) -> (-18.2627, -22.7953)
  line L48 (-19.9667, -26) -> (-19.0867, -24.4125)
  line L49 (-20.9015, -27.5558) -> (-19.9667, -26)
  line L50 (-21.89, -29.078) -> (-20.9015, -27.5558)
  line L51 (-22.9311, -30.5648) -> (-21.89, -29.078)
  line L52 (-24.0234, -32.0144) -> (-22.9311, -30.5648)
  line L53 (-25.1657, -33.425) -> (-24.0234, -32.0144)
  line L54 (-26.3565, -34.7948) -> (-25.1657, -33.425)
  line L55 (-27.5943, -36.1222) -> (-26.3565, -34.7948)
  line L56 (-28.8778, -37.4057) -> (-27.5943, -36.1222)
  line L57 (-30.2052, -38.6435) -> (-28.8778, -37.4057)
  line L58 (-31.575, -39.8343) -> (-30.2052, -38.6435)
  line L59 (-32.9856, -40.9766) -> (-31.575, -39.8343)
  line L60 (-34.4352, -42.0689) -> (-32.9856, -40.9766)
  line L61 (-35.922, -43.11) -> (-34.4352, -42.0689)
  line L62 (-37.4442, -44.0985) -> (-35.922, -43.11)
  line L63 (-39, -45.0333) -> (-37.4442, -44.0985)
  line L64 (-40.5875, -45.9133) -> (-39, -45.0333)
  line L65 (-42.2047, -46.7373) -> (-40.5875, -45.9133)
  line L66 (-43.8497, -47.5044) -> (-42.2047, -46.7373)
  line L67 (-54.4248, -23.7522) -> (-43.8497, -47.5044)
  line L68 (-53.6024, -23.3686) -> (-54.4248, -23.7522)
  line L69 (-52.7937, -22.9566) -> (-53.6024, -23.3686)
  line L70 (-52, -22.5167) -> (-52.7937, -22.9566)
  line L71 (-51.2221, -22.0493) -> (-52, -22.5167)
  line L72 (-50.461, -21.555) -> (-51.2221, -22.0493)
  line L73 (-49.7176, -21.0344) -> (-50.461, -21.555)
  line L74 (-48.9928, -20.4883) -> (-49.7176, -21.0344)
  line L75 (-48.2875, -19.9172) -> (-48.9928, -20.4883)
  line L76 (-47.6026, -19.3218) -> (-48.2875, -19.9172)
  line L77 (-46.9389, -18.7028) -> (-47.6026, -19.3218)
  line L78 (-46.2972, -18.0611) -> (-46.9389, -18.7028)
  line L79 (-45.6782, -17.3974) -> (-46.2972, -18.0611)
  line L80 (-45.0828, -16.7125) -> (-45.6782, -17.3974)
  line L81 (-44.5117, -16.0072) -> (-45.0828, -16.7125)
  line L82 (-43.9656, -15.2824) -> (-44.5117, -16.0072)
  line L83 (-43.445, -14.539) -> (-43.9656, -15.2824)
  line L84 (-42.9507, -13.7779) -> (-43.445, -14.539)
  line L85 (-42.4833, -13) -> (-42.9507, -13.7779)
  line L86 (-42.0434, -12.2063) -> (-42.4833, -13)
  line L87 (-41.6314, -11.3976) -> (-42.0434, -12.2063)
  line L88 (-41.2478, -10.5752) -> (-41.6314, -11.3976)
  line L89 (-40.8932, -9.7398) -> (-41.2478, -10.5752)
  line L90 (-40.568, -8.8925) -> (-40.8932, -9.7398)
  line L91 (-40.2725, -8.0344) -> (-40.568, -8.8925)
  line L92 (-40.0072, -7.1666) -> (-40.2725, -8.0344)
  line L93 (-39.7723, -6.29) -> (-40.0072, -7.1666)
  line L94 (-39.5682, -5.4057) -> (-39.7723, -6.29)
  line L95 (-39.395, -4.5149) -> (-39.5682, -5.4057)
  line L96 (-39.253, -3.6185) -> (-39.395, -4.5149)
  line L97 (-39.1424, -2.7177) -> (-39.253, -3.6185)
  line L98 (-39.0633, -1.8137) -> (-39.1424, -2.7177)
  line L99 (-39.0158, -0.9074) -> (-39.0633, -1.8137)
  line L100 (-39, 0) -> (-39.0158, -0.9074)
  line L101 (-39.0158, 0.9074) -> (-39, 0)
  line L102 (-39.0633, 1.8137) -> (-39.0158, 0.9074)
  line L103 (-39.1424, 2.7177) -> (-39.0633, 1.8137)
  line L104 (-39.253, 3.6185) -> (-39.1424, 2.7177)
  line L105 (-39.395, 4.5149) -> (-39.253, 3.6185)
  line L106 (-39.5682, 5.4057) -> (-39.395, 4.5149)
  line L107 (-39.7723, 6.29) -> (-39.5682, 5.4057)
  line L108 (-40.0072, 7.1666) -> (-39.7723, 6.29)
  line L109 (-40.2725, 8.0344) -> (-40.0072, 7.1666)
  line L110 (-40.568, 8.8925) -> (-40.2725, 8.0344)
  line L111 (-40.8932, 9.7398) -> (-40.568, 8.8925)
  line L112 (-41.2478, 10.5752) -> (-40.8932, 9.7398)
  line L113 (-41.6314, 11.3976) -> (-41.2478, 10.5752)
  line L114 (-42.0434, 12.2063) -> (-41.6314, 11.3976)
  line L115 (-42.4833, 13) -> (-42.0434, 12.2063)
  line L116 (-42.9507, 13.7779) -> (-42.4833, 13)
  line L117 (-43.445, 14.539) -> (-42.9507, 13.7779)
  line L118 (-43.9656, 15.2824) -> (-43.445, 14.539)
  line L119 (-44.5117, 16.0072) -> (-43.9656, 15.2824)
  line L120 (-45.0828, 16.7125) -> (-44.5117, 16.0072)
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extrude "Extrude47" cut sketch "Restore cam service opening after obsolete bore closure" along normal blind 12.2
work_plane "WorkPlane48" AlongDistance -15.4 ExtraOffset 0
sketch "Fill former M5 stop nut pocket" plane through (-15.4, 0, 0) normal (1, 0, 0) x axis (0, 0, -1)
  circle C1 centre (-79.6754, -33.9652) radius 4.9
extrude "Extrude48" add sketch "Fill former M5 stop nut pocket" along normal blind 6.4
work_plane "WorkPlane49" AlongDistance -36 ExtraOffset 0
sketch "Fill former M5 stop bore" plane through (-36, 0, 0) normal (1, 0, 0) x axis (0, 0, -1)
  circle C1 centre (-79.6754, -33.9652) radius 2.71
extrude "Extrude49" add sketch "Fill former M5 stop bore" along normal blind 27
work_plane "WorkPlane50" AlongDistance -36.1 ExtraOffset 0
sketch "M3 stop reinforcement bore" plane through (-36.1, 0, 0) normal (1, 0, 0) x axis (0, 0, -1)
  circle C1 centre (-79.6754, -33.9652) radius 1.7
extrude "Extrude50" cut sketch "M3 stop reinforcement bore" along normal blind 27.2
work_plane "WorkPlane51" AlongDistance -13.5 ExtraOffset 0
sketch "Captive M3 locknut stop pocket" plane through (-13.5, 0, 0) normal (1, 0, 0) x axis (0, 0, -1)
  line L1 (-82.5754, -32.2908) -> (-79.6754, -30.6165)
  line L2 (-82.5754, -35.6395) -> (-82.5754, -32.2908)
  line L3 (-79.6754, -37.3138) -> (-82.5754, -35.6395)
  line L4 (-76.7754, -35.6395) -> (-79.6754, -37.3138)
  line L5 (-76.7754, -32.2908) -> (-76.7754, -35.6395)
  line L6 (-79.6754, -30.6165) -> (-76.7754, -32.2908)
extrude "Extrude51" cut sketch "Captive M3 locknut stop pocket" along normal blind 4.6
work_plane "WorkPlane52" AlongDistance -15.4 ExtraOffset 0
sketch "Fill former M5 stop nut pocket (1)" plane through (-15.4, 0, 0) normal (1, 0, 0) x axis (0, 0, -1)
  circle C1 centre (-79.6754, 33.9652) radius 4.9
extrude "Extrude52" add sketch "Fill former M5 stop nut pocket (1)" along normal blind 6.4
work_plane "WorkPlane53" AlongDistance -36 ExtraOffset 0
sketch "Fill former M5 stop bore (1)" plane through (-36, 0, 0) normal (1, 0, 0) x axis (0, 0, -1)
  circle C1 centre (-79.6754, 33.9652) radius 2.71
extrude "Extrude53" add sketch "Fill former M5 stop bore (1)" along normal blind 27
work_plane "WorkPlane54" AlongDistance -36.1 ExtraOffset 0
sketch "M3 stop reinforcement bore (1)" plane through (-36.1, 0, 0) normal (1, 0, 0) x axis (0, 0, -1)
  circle C1 centre (-79.6754, 33.9652) radius 1.7
extrude "Extrude54" cut sketch "M3 stop reinforcement bore (1)" along normal blind 27.2
work_plane "WorkPlane55" AlongDistance -13.5 ExtraOffset 0
sketch "Captive M3 locknut stop pocket (1)" plane through (-13.5, 0, 0) normal (1, 0, 0) x axis (0, 0, -1)
  line L1 (-82.5754, 35.6395) -> (-79.6754, 37.3138)
  line L2 (-82.5754, 32.2908) -> (-82.5754, 35.6395)
  line L3 (-79.6754, 30.6165) -> (-82.5754, 32.2908)
  line L4 (-76.7754, 32.2908) -> (-79.6754, 30.6165)
  line L5 (-76.7754, 35.6395) -> (-76.7754, 32.2908)
  line L6 (-79.6754, 37.3138) -> (-76.7754, 35.6395)
extrude "Extrude55" cut sketch "Captive M3 locknut stop pocket (1)" along normal blind 4.6
work_plane "WorkPlane1" AlongDistance 50 ExtraOffset 0
sketch "Rail vertical M5x16 (-30, -1)" plane through (0, 0, 50) normal (0, 0, 1) x axis (1, 0, 0)
  circle C1 centre (-30, -85) radius 2.5
extrude "Extrude1" new body sketch "Rail vertical M5x16 (-30, -1)" along normal blind 16 bodies "HARDWARE Rail vertical M5x16 (-30, -1)"
work_plane "WorkPlane2" AlongDistance 66 ExtraOffset 0
sketch "Button head" plane through (0, 0, 66) normal (0, 0, 1) x axis (1, 0, 0)
  circle C1 centre (-30, -85) radius 4.75
extrude "Extrude2" add sketch "Button head" along normal blind 2.75
work_plane "WorkPlane1" AlongDistance 63 ExtraOffset 0
sketch "Rail M5 metal spacer 3mm (-30, -1)" plane through (0, 0, 63) normal (0, 0, 1) x axis (1, 0, 0)
  circle C1 centre (-30, -85) radius 5
extrude "Extrude1" new body sketch "Rail M5 metal spacer 3mm (-30, -1)" along normal blind 3 bodies "HARDWARE Rail M5 metal spacer 3mm (-30, -1)"
work_plane "WorkPlane2" AlongDistance 62.9 ExtraOffset 0
sketch "Washer clearance" plane through (0, 0, 62.9) normal (0, 0, 1) x axis (1, 0, 0)
  circle C1 centre (-30, -85) radius 2.7
extrude "Extrude2" cut sketch "Washer clearance" along normal blind 3.2
work_plane "WorkPlane1" AlongDistance 50 ExtraOffset 0
sketch "Rail vertical M5x16 (-30, 1)" plane through (0, 0, 50) normal (0, 0, 1) x axis (1, 0, 0)
  circle C1 centre (-30, 85) radius 2.5
extrude "Extrude1" new body sketch "Rail vertical M5x16 (-30, 1)" along normal blind 16 bodies "HARDWARE Rail vertical M5x16 (-30, 1)"
work_plane "WorkPlane2" AlongDistance 66 ExtraOffset 0
sketch "Button head" plane through (0, 0, 66) normal (0, 0, 1) x axis (1, 0, 0)
  circle C1 centre (-30, 85) radius 4.75
extrude "Extrude2" add sketch "Button head" along normal blind 2.75
work_plane "WorkPlane1" AlongDistance 63 ExtraOffset 0
sketch "Rail M5 metal spacer 3mm (-30, 1)" plane through (0, 0, 63) normal (0, 0, 1) x axis (1, 0, 0)
  circle C1 centre (-30, 85) radius 5
extrude "Extrude1" new body sketch "Rail M5 metal spacer 3mm (-30, 1)" along normal blind 3 bodies "HARDWARE Rail M5 metal spacer 3mm (-30, 1)"
work_plane "WorkPlane2" AlongDistance 62.9 ExtraOffset 0
sketch "Washer clearance" plane through (0, 0, 62.9) normal (0, 0, 1) x axis (1, 0, 0)
  circle C1 centre (-30, 85) radius 2.7
extrude "Extrude2" cut sketch "Washer clearance" along normal blind 3.2
work_plane "WorkPlane1" AlongDistance 50 ExtraOffset 0
sketch "Rail vertical M5x16 (30, -1)" plane through (0, 0, 50) normal (0, 0, 1) x axis (1, 0, 0)
  circle C1 centre (30, -85) radius 2.5
extrude "Extrude1" new body sketch "Rail vertical M5x16 (30, -1)" along normal blind 16 bodies "HARDWARE Rail vertical M5x16 (30, -1)"
work_plane "WorkPlane2" AlongDistance 66 ExtraOffset 0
